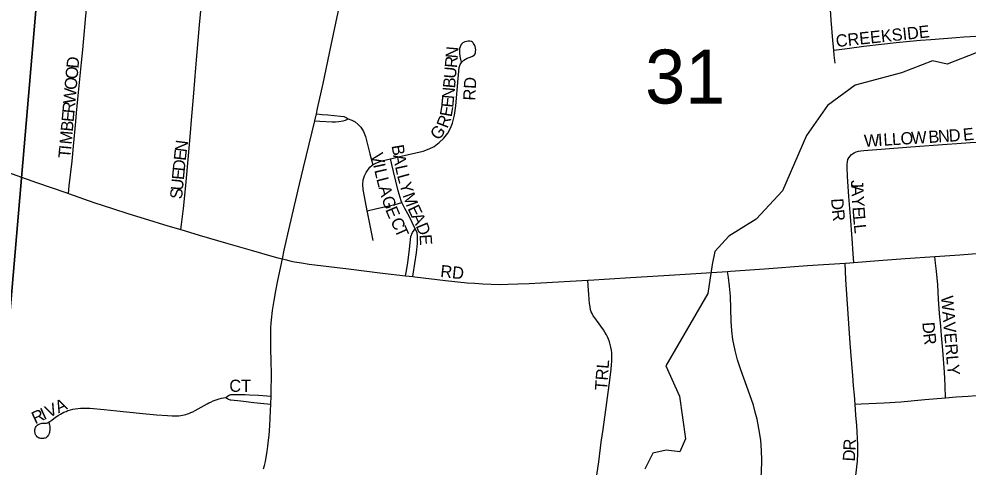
# Model space of a CAD drawing. Extents: x 1410790 to 1770854, y 448063 to 770588.
# Drawn here: x 1527623 to 1531514, y 625208 to 627043 of the extents above; entities that cross this region are included whole.
import ezdxf

# ---------------------------------------------------------------- set-up
doc = ezdxf.new("R2010")
doc.units = 0
for name, color, linetype in [('GM_X_City_Street', 7, 'Continuous'), ('GM_X_City_Street_Text', 7, 'Continuous'), ('GM_X_Minor_River', 7, 'Continuous'), ('GM_X_Section', 7, 'Continuous'), ('GM_X_Section_Text', 7, 'Continuous')]:
    doc.layers.add(name, color=color, linetype=linetype)

msp = doc.modelspace()

# ---------------------------------------------------------------- linework, layer by layer
at = {"layer": 'GM_X_City_Street'}
for points in [[(1530963.7, 626915.2), (1530959.7, 626954.3), (1530953.4, 627039.1), (1530948.8, 627101.3), (1530943.8, 627159.6), (1530940.3, 627210.7), (1530936.7, 627263.5), (1530932.7, 627322.4)], [(1527825.5, 626328), (1527829.4, 626359.9), (1527841.5, 626460.4), (1527846.9, 626522.1), (1527856.2, 626623.2), (1527859.4, 626659), (1527864.5, 626714), (1527879.4, 626864.9), (1527884.8, 626916.9), (1527895.6, 627040.4), (1527903.8, 627125.3), (1527912.3, 627203.6), (1527920.6, 627274.8), (1527924.3, 627306.6)], [(1528287.2, 626180.1), (1528289.6, 626201.1), (1528297.3, 626267.2), (1528306.7, 626361.4), (1528318.6, 626482), (1528326.3, 626576.7), (1528330.7, 626629), (1528338.7, 626722), (1528343.6, 626790.3), (1528347.9, 626842.6), (1528363.6, 627018.8), (1528373.9, 627133.1), (1528381.3, 627204.8), (1528386.7, 627262.5)], [(1528842.5, 626654.4), (1528847.6, 626676.8), (1528870.2, 626778.9), (1528903.2, 626935.6), (1528931.8, 627071.1), (1528951, 627170.4), (1528956.7, 627201.8)], [(1530963.7, 626915.2), (1531018.6, 626922.5), (1531087.7, 626931.2), (1531159.6, 626940.2), (1531219, 626946.9), (1531276, 626952.2), (1531319, 626955.9), (1531361.4, 626959.1), (1531465.6, 626967.2), (1531496.5, 626969.5), (1531523.1, 626971), (1531568.2, 626973.8), (1531640.8, 626978.6), (1531676.9, 626980.9), (1531712.9, 626984.2), (1531727.4, 626986.3), (1531739.1, 626988.6), (1531751.4, 626991.5), (1531760.6, 626994.9), (1531766.9, 626998.1), (1531772.4, 627001.6), (1531776.5, 627004.9), (1531779.1, 627008.3), (1531782.3, 627012.7)], [(1529146.9, 626470.7), (1529190.1, 626481.6), (1529279.6, 626502.1), (1529304.3, 626510.8), (1529324.7, 626521.2), (1529345.8, 626536.8), (1529364.7, 626554.9), (1529380.9, 626575.5), (1529392.4, 626595.3), (1529400.9, 626616.6), (1529408.9, 626648.3), (1529414.5, 626687.3), (1529423.3, 626798.8), (1529428, 626844.4), (1529431.9, 626856.9), (1529437.1, 626865.2), (1529446.6, 626874.2), (1529460.9, 626882.2), (1529472.9, 626886.6), (1529482.3, 626890.8), (1529488.7, 626894.2), (1529491.2, 626896.7), (1529493.3, 626899.8), (1529494.7, 626903.7), (1529495.5, 626909.8), (1529495.7, 626916.9), (1529494.6, 626923.9), (1529493.4, 626930), (1529491.7, 626934.4), (1529489.8, 626939), (1529486.7, 626943.1), (1529485, 626945.6), (1529482.2, 626948), (1529477.9, 626950.5), (1529471.5, 626951.9), (1529464.7, 626952.1), (1529457.6, 626951.1), (1529451.3, 626949.2), (1529442.6, 626944.8), (1529438.7, 626941.3), (1529435.9, 626937.9), (1529431.5, 626929.1), (1529429.7, 626921.8), (1529428.9, 626916.2), (1529429, 626908.7), (1529429.2, 626901), (1529430.5, 626891.5), (1529432.4, 626882.3), (1529436.7, 626868.2)], [(1530969.1, 626861.9), (1530965.7, 626895.4), (1530963.7, 626915.2)], [(1526395.2, 626865.9), (1526410.7, 626859), (1526627.7, 626766.5), (1526685.4, 626742.2), (1526751.4, 626715.7), (1526902, 626657.7), (1527010.1, 626617.2), (1527188.3, 626552.7), (1527392.6, 626480.9), (1527552.9, 626423.2), (1527695.2, 626372.9), (1527815.2, 626331.6), (1527825.5, 626328)], [(1528836, 626625.6), (1528842.5, 626654.4)], [(1528842.5, 626654.4), (1528865.7, 626652.2), (1528889.8, 626649.8), (1528941.2, 626645.3), (1528954.8, 626643), (1528965, 626639.6), (1528973, 626634.2)], [(1528702.9, 626059.7), (1528711, 626095.8), (1528734, 626197.3), (1528757.8, 626302.4), (1528773, 626366.6), (1528789.5, 626434.3), (1528825.7, 626580.9), (1528836, 626625.6)], [(1528836, 626625.6), (1528856.9, 626624.5), (1528907.1, 626621.8), (1528921.1, 626622.2), (1528935, 626623.4), (1528952.4, 626625.6), (1528962.4, 626629.1), (1528973, 626634.2)], [(1528973, 626634.2), (1528987.5, 626628.8), (1529000.8, 626621.3), (1529013.9, 626611.3), (1529024.9, 626599.1), (1529035.3, 626582.3), (1529043.7, 626560.9), (1529061.8, 626490.6), (1529073.5, 626445.6)], [(1531041.1, 626490.4), (1531048, 626494.9), (1531056, 626498.4), (1531065.1, 626501.1), (1531075, 626502.8), (1531087.4, 626504.3), (1531158.7, 626509.5), (1531279.2, 626519), (1531429, 626530.2), (1531468.2, 626532.9), (1531523.7, 626536.3), (1531605, 626541.4), (1531687, 626545.6), (1531721.4, 626547.4)], [(1531046.3, 626045.5), (1531043.7, 626080.2), (1531038.8, 626143.3), (1531031.9, 626233.4), (1531026.1, 626315.9), (1531020.5, 626397.1), (1531018.5, 626435.6), (1531018.4, 626446.3), (1531019.6, 626457.8), (1531022, 626466.9), (1531026.2, 626474.3), (1531031.7, 626481.5), (1531036.9, 626487.2), (1531041.1, 626490.4)], [(1529073.5, 626445.6), (1529085.8, 626452.7), (1529110.6, 626461.5), (1529146.9, 626470.7)], [(1529193.2, 626290.5), (1529189.7, 626298.3), (1529177.3, 626338.8), (1529158.2, 626418.3), (1529152, 626447.1), (1529146.9, 626470.7)], [(1529051.3, 626257.3), (1529040.3, 626316.2), (1529033.8, 626345), (1529032.5, 626364.6), (1529034.7, 626384.1), (1529039.3, 626399.8), (1529046.8, 626414.4), (1529062.1, 626435.7), (1529071.7, 626444.5), (1529073.5, 626445.6)], [(1527825.5, 626328), (1527930.4, 626291.7), (1528006.2, 626266.1), (1528073.9, 626244.4), (1528136.3, 626225.3), (1528233.5, 626195.9), (1528287.2, 626180.1)], [(1529051.3, 626257.3), (1529084.7, 626264.6), (1529139.9, 626277.4), (1529165.5, 626283.6), (1529193.2, 626290.5)], [(1529075.7, 626136), (1529053.5, 626245.3), (1529051.3, 626257.3)], [(1529248, 626183.3), (1529235.7, 626209.4), (1529222.7, 626235.5), (1529205.1, 626266.3), (1529193.2, 626290.5)], [(1528287.2, 626180.1), (1528362.1, 626158), (1528479.7, 626123.3), (1528574.7, 626095.5), (1528659.8, 626071.2), (1528684, 626064.5), (1528702.9, 626059.7)], [(1529207.8, 625991.1), (1529210.1, 626004.4), (1529217.1, 626044.3), (1529224.9, 626099.7), (1529229.4, 626152.2), (1529236.8, 626168.8), (1529248, 626183.3)], [(1529238.1, 625987.5), (1529239.6, 625997.1), (1529253.6, 626084.4), (1529257.5, 626123.4), (1529257.7, 626152.8), (1529255.5, 626168.7), (1529248, 626183.3)], [(1531046.3, 626045.5), (1531147.7, 626052.9), (1531257.1, 626061.2), (1531378.2, 626069.9)], [(1531378.2, 626069.9), (1531481.1, 626077.2), (1531597.8, 626085.9), (1531695.6, 626093.1)], [(1531421.7, 625491.3), (1531419.9, 625539.9), (1531418.9, 625570), (1531417.8, 625596.3), (1531410.7, 625686.8), (1531405.4, 625745.9), (1531402.2, 625784.8), (1531397.9, 625836.8), (1531393.5, 625895.5), (1531390, 625954.5), (1531384.7, 626010.1), (1531381.1, 626042.6), (1531378.2, 626069.9)], [(1528656.9, 625497.5), (1528657.6, 625512.9), (1528658, 625586.2), (1528657.1, 625643.9), (1528655.8, 625688.6), (1528655, 625747.7), (1528655.8, 625778.9), (1528657.1, 625795.4), (1528658.5, 625811), (1528662.8, 625848.8), (1528668.9, 625889.6), (1528675.8, 625929.1), (1528682.7, 625965.1), (1528696.2, 626029.4), (1528702.9, 626059.7)], [(1528702.9, 626059.7), (1528719.7, 626055.6), (1528733.1, 626052.4), (1528753.1, 626048.6), (1528780.9, 626043.9), (1528813, 626038.9), (1528974.2, 626019.2), (1529113.8, 626002.2), (1529207.8, 625991.1)], [(1530528.3, 626009.1), (1530540.9, 626010), (1530679.4, 626019.9), (1530856, 626032.7), (1531010.8, 626043.1)], [(1531010.8, 626043.1), (1531029.7, 626044.3), (1531046.3, 626045.5)], [(1531051.4, 625464.8), (1531048.7, 625501.3), (1531045.4, 625540.4), (1531041.9, 625582.9), (1531037.2, 625646.9), (1531031.6, 625714.3), (1531013.2, 625975.4), (1531010.8, 626043.1)], [(1529207.8, 625991.1), (1529238.1, 625987.5)], [(1529238.1, 625987.5), (1529245.7, 625986.6), (1529372.5, 625971.8), (1529460.1, 625962.7), (1529491.8, 625960.1), (1529524.7, 625958.1), (1529559.1, 625956.6), (1529594.3, 625955.8), (1529628.1, 625956.2), (1529668.5, 625957.6), (1529714.5, 625959.2), (1529762.2, 625961.4), (1529955.2, 625973)], [(1529955.2, 625973), (1529958.5, 625973.2), (1530130.1, 625984.4), (1530266.7, 625992.6), (1530376.9, 625999.1), (1530528.3, 626009.1)], [(1530658.1, 625075.3), (1530663.3, 625138.9), (1530666.9, 625184.4), (1530668.8, 625236.2), (1530667.8, 625275.2), (1530664.1, 625317.3), (1530656.9, 625365.6), (1530649.1, 625403.9), (1530642.1, 625432.3), (1530634.1, 625460.5), (1530619.9, 625503.8), (1530607.7, 625537.7), (1530582.4, 625605.3), (1530569, 625646), (1530559.1, 625684.4), (1530549.9, 625729.6), (1530545.3, 625765.6), (1530542.7, 625805.2), (1530539.8, 625906.8), (1530536.6, 625949), (1530531.7, 625984.4), (1530528.3, 626009.1)], [(1529982, 625101.6), (1530000.2, 625228.5), (1530010.7, 625309.8), (1530018.3, 625361.7), (1530033.5, 625472.2), (1530045.7, 625563.4), (1530050.6, 625607.9), (1530053.8, 625642.1), (1530054.5, 625655), (1530054.5, 625665), (1530053.5, 625675.6), (1530052.1, 625685.6), (1530050, 625698.1), (1530047.5, 625709.3), (1530044, 625720.3), (1530040.4, 625730.8), (1530036.1, 625740.7), (1530031.5, 625749.3), (1530025.3, 625760.6), (1530019.6, 625769.6), (1529991.1, 625809), (1529984.1, 625818), (1529977.8, 625827.1), (1529973.2, 625835.8), (1529969.6, 625843.5), (1529967, 625852), (1529964.6, 625863.4), (1529962.5, 625877.9), (1529960.9, 625893.5), (1529958.9, 625915.1), (1529958, 625930.7), (1529955.2, 625973)], [(1527746.1, 625390.2), (1527747.6, 625380.6), (1527749, 625371.6), (1527749.4, 625363.3), (1527749.1, 625357.6), (1527748.7, 625353.7), (1527747.8, 625348.9), (1527746.7, 625344.8), (1527745.7, 625342), (1527744.4, 625339.2), (1527740.4, 625333.8), (1527738.5, 625331.4), (1527736.5, 625329.7), (1527734, 625327.7), (1527730.9, 625326.2), (1527727.9, 625325.1), (1527724.2, 625324.2), (1527720.7, 625323.8), (1527716.6, 625323.8), (1527712.5, 625324.2), (1527708.8, 625325.1), (1527705.5, 625326.2), (1527702.5, 625327.7), (1527699.2, 625329.9), (1527696.8, 625331.8), (1527694.3, 625334.6), (1527692.5, 625337.5), (1527690.8, 625341.1), (1527689.7, 625344), (1527688.8, 625347.2), (1527688.2, 625350.5), (1527688, 625354.4), (1527688.2, 625359.4), (1527689, 625363.7), (1527689.9, 625366.5), (1527691, 625369.2), (1527693.1, 625372.9), (1527695.3, 625375.9), (1527698.2, 625378.9), (1527701.8, 625381.7), (1527705.3, 625383.7), (1527708.8, 625385), (1527712.7, 625386.1), (1527716.6, 625386.5), (1527719.4, 625386.5), (1527726.6, 625386.5), (1527732.9, 625387.2), (1527735.9, 625387.8), (1527740, 625389.1), (1527744.4, 625391.1), (1527749.8, 625393.9), (1527753.7, 625396.3), (1527757.2, 625398.9), (1527766.3, 625406), (1527771.5, 625410.2), (1527776.5, 625414.1), (1527783.2, 625418.6), (1527792.8, 625424.5), (1527799.5, 625428.2), (1527807.3, 625431.7), (1527816, 625435.3), (1527823.8, 625438.4), (1527833.6, 625441.4), (1527843.8, 625444.2), (1527854, 625446.4), (1527863.9, 625447.9), (1527875.7, 625448.8), (1527886.5, 625449.2), (1527901.3, 625449), (1527913.8, 625448.4), (1527972.1, 625442.9), (1528024.2, 625437.7), (1528117.1, 625428.6), (1528186.7, 625421.9), (1528232.4, 625418.4), (1528250.5, 625417.5), (1528266.7, 625417.3), (1528276.5, 625417.7), (1528286.5, 625418.8), (1528294.1, 625419.9), (1528300.8, 625421.2), (1528307.5, 625423), (1528313.8, 625424.9), (1528320.1, 625427.1), (1528327.9, 625430.3), (1528336.2, 625434), (1528345.5, 625438.6), (1528394.5, 625466.4), (1528402.1, 625470.3), (1528409.5, 625473.7), (1528419.4, 625478.3), (1528427.8, 625481.8), (1528435.5, 625484.4), (1528444, 625487), (1528452.8, 625489.1), (1528462, 625490.9), (1528471.5, 625492.2)], [(1528471.5, 625492.2), (1528478.3, 625497.8), (1528484.2, 625501.7), (1528487.9, 625503.2), (1528491.1, 625504.1), (1528495.7, 625504.6), (1528501.4, 625504.8), (1528534.8, 625504.8), (1528550.6, 625504.6), (1528567.8, 625503.9), (1528605.1, 625501.7), (1528656.9, 625497.5)], [(1528471.5, 625492.2), (1528477.5, 625488.1), (1528481.8, 625485.5), (1528485.3, 625484), (1528489.4, 625482.9), (1528492.2, 625482.4), (1528532.9, 625478.3), (1528585.9, 625472.4), (1528612.8, 625469.4), (1528655.6, 625464.6)], [(1528655.6, 625464.6), (1528656.9, 625497.5)], [(1531051.4, 625464.8), (1531075.8, 625466), (1531170.6, 625470.8), (1531239.4, 625474.7), (1531337.3, 625483.5), (1531421.7, 625491.3)], [(1531421.7, 625491.3), (1531466.3, 625494.7), (1531514.3, 625498.4), (1531583.7, 625503.7), (1531625, 625506.8), (1531671.4, 625510), (1531713.8, 625512.5), (1531779.1, 625515.1), (1531793, 625515.2)], [(1528625.7, 625199.8), (1528629.6, 625214), (1528633.6, 625230.1), (1528637, 625248), (1528640.5, 625270.5), (1528643.7, 625292.8), (1528646.6, 625317.4), (1528648.5, 625336.6), (1528650.1, 625356.5), (1528651.5, 625377.9), (1528654.6, 625438.2), (1528655.6, 625464.6)], [(1531040.7, 625043), (1531044.3, 625083.2), (1531046.2, 625104.6), (1531053.9, 625172.3), (1531061.1, 625230.8), (1531062.8, 625263.1), (1531062.2, 625298.8), (1531057.8, 625377.2), (1531054.9, 625419.6), (1531051.4, 625464.8)]]:
    msp.add_lwpolyline(points, dxfattribs=at)
at = {"layer": 'GM_X_Minor_River'}
msp.add_lwpolyline([(1531547.5, 626903.7), (1531428.4, 626858.2), (1531368.6, 626871.6), (1531241.5, 626822.2), (1531052.2, 626772.2), (1530938.5, 626688.4), (1530852, 626566), (1530753.5, 626339.5), (1530645.2, 626223.5), (1530533.7, 626153.8), (1530476.4, 626090.8), (1530465.4, 626036.9), (1530447.1, 625919), (1530275.2, 625621.8), (1530330.9, 625498.2), (1530355.6, 625323.2), (1530332.5, 625269.5), (1530276.6, 625276.8), (1530222.3, 625263.9), (1530189, 625198.5)], dxfattribs=at)
at = {"layer": 'GM_X_Section'}
for points in [[(1527942.6, 630003), (1527484, 624666.3), (1522801.4, 625129.5), (1522174.5, 625186.4), (1522667.1, 630530.5)], [(1533261.2, 629430.7), (1532828.2, 624183.7), (1528025, 624614.9), (1527484, 624666.3), (1527942.6, 630003)]]:
    msp.add_lwpolyline(points, close=True, dxfattribs=at)

# ---------------------------------------------------------------- texts
at = {"layer": 'GM_X_City_Street_Text'}
for s, rotation, p in [('CREEKSIDE', 6.0117, (1530974.8, 626927.7)), ('N', 84.9768, (1529421.5, 626880.3)), ('D', 84.2633, (1527866.6, 626838.5)), ('R', 84.9782, (1529418.1, 626840.9)), ('O', 84.8897, (1527862.7, 626794.8)), ('U', 84.9869, (1529414.2, 626797)), ('O', 84.8897, (1527858.8, 626751)), ('RD', 86.9884, (1529493.9, 626707.6)), ('B', 84.9898, (1529410.8, 626757.6)), ('W', 84.8929, (1527853.7, 626694)), ('E', 84.5167, (1529403.5, 626678.3)), ('N', 84.9248, (1529406.8, 626713.7)), ('R', 84.9007, (1527850.2, 626654.6)), ('E', 80.1608, (1529396.9, 626639.5)), ('E', 84.885, (1527847, 626619.5)), ('R', 68.7829, (1529379.6, 626592.1)), ('B', 84.8814, (1527843.5, 626580.1)), ('M', 84.8958, (1527838.8, 626527.5)), ('G', 49.6962, (1529341.9, 626543)), ('W', 3.5328, (1531089.7, 626518.6)), ('I', 3.551, (1531146.8, 626522.1)), ('L', 3.5269, (1531168.8, 626523.4)), ('L', 3.555, (1531203.9, 626525.6)), ('O', 3.5429, (1531239.1, 626527.8)), ('W', 3.5328, (1531283, 626530.5)), ('B', 3.5503, (1531353.3, 626534.8)), ('N', 3.5429, (1531392.8, 626537.3)), ('D', 3.5211, (1531436.7, 626540)), ('E', 5.808, (1531496, 626543.7)), ('N', 82.5577, (1528310.6, 626495.5)), ('T', 84.8847, (1527833.7, 626470.5)), ('I', 84.8941, (1527836.9, 626505.6)), ('E', 83.607, (1528306.7, 626460.7)), ('V', 281.3957, (1529066, 626489.7)), ('B', 279.5501, (1529150.4, 626523.9)), ('D', 84.4177, (1528302.4, 626417.1)), ('A', 279.5522, (1529156.9, 626484.8)), ('E', 84.4283, (1528299, 626382.1)), ('I', 282.1117, (1529074.8, 626445.9)), ('L', 282.9969, (1529079.6, 626423.6)), ('L', 282.08, (1529164.7, 626439.1)), ('U', 84.4068, (1528294.7, 626338.3)), ('L', 284.537, (1529087.9, 626387.9)), ('L', 285.1925, (1529172.7, 626401.8)), ('Y', 285.6144, (1529182.1, 626367.4)), ('J', 273.3909, (1531033.7, 626382.1)), ('S', 84.4172, (1528291.3, 626303.3)), ('A', 285.5221, (1529096.9, 626352.9)), ('A', 273.3931, (1531035, 626360.2)), ('G', 287.6508, (1529109.3, 626308.5)), ('M', 289.9035, (1529195.2, 626321.2)), ('D', 273.4005, (1530953.1, 626306.9)), ('Y', 273.3992, (1531037.6, 626316.2)), ('E', 292.7927, (1529124.3, 626262)), ('E', 295.6987, (1529215.3, 626266.4)), ('R', 277.1405, (1530956, 626259.5)), ('E', 273.7302, (1531040.2, 626272)), ('C', 295.3485, (1529144.7, 626215.3)), ('A', 295.4408, (1529230.5, 626234.7)), ('L', 275.3512, (1531042.6, 626235.3)), ('T', 293.9001, (1529161.5, 626179.8)), ('D', 292.3879, (1529249.1, 626195.7)), ('L', 275.9832, (1531045.9, 626199.7)), ('E', 273.9104, (1529264.9, 626159.1)), ('RD', 353.9832, (1529348.9, 625986.1)), ('WAVERLY', 274.9684, (1531403.3, 625907)), ('D', 274.1121, (1531327, 625799.8)), ('R', 277.419, (1531330.5, 625752.9)), ('TRL', 85.6032, (1530033.7, 625519.9)), ('CT', 0, (1528485.5, 625515.4)), ('A', 25.1232, (1527784.9, 625427.3)), ('R', 25.1313, (1527689.3, 625382.4)), ('I', 25.1511, (1527725.2, 625399.2)), ('V', 25.1475, (1527745.1, 625408.6)), ('R', 87.7333, (1531052.7, 625274.3)), ('D', 86.6541, (1531050.1, 625229.4))]:
    msp.add_text(s, height=50, rotation=rotation, dxfattribs=at).set_placement(p)
at = {"layer": 'GM_X_Section_Text'}
msp.add_text('31', height=221, rotation=0, dxfattribs=at).set_placement((1530190.5, 626696.5))

doc.saveas('drawing.dxf')
